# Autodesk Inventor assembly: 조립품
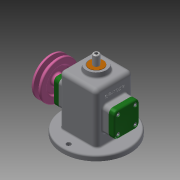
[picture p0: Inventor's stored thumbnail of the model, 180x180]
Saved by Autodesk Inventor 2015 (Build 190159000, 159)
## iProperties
Created: 2021-08
Part Number: 조립품
Document SubType Name: Assembly
Designer: 104-00
Author: 104-00
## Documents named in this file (16)
- C:\Users\104-00\Desktop\710806V1026\조립품.iam
- C:\Users\104-00\Desktop\710806V1026\V벨트풀리.ipt
- C:\Users\104-00\Desktop\710806V1026\고정핀 1.2x8.ipt
- C:\Users\104-00\Desktop\710806V1026\뒤커버.ipt
- C:\Users\104-00\Desktop\710806V1026\링크.ipt
- C:\Users\104-00\Desktop\710806V1026\멈춤나사 M3x8.ipt
- C:\Users\104-00\Desktop\710806V1026\베어링 12x32x10.ipt
- C:\Users\104-00\Desktop\710806V1026\본체.ipt
- C:\Users\104-00\Desktop\710806V1026\볼트 M4.ipt
- C:\Users\104-00\Desktop\710806V1026\부시.ipt
- C:\Users\104-00\Desktop\710806V1026\슬라이드.ipt
- C:\Users\104-00\Desktop\710806V1026\앞커버.ipt
- C:\Users\104-00\Desktop\710806V1026\오일 실 12 25 7.ipt
- C:\Users\104-00\Desktop\710806V1026\키 4x4x10.ipt
- C:\Users\104-00\Desktop\710806V1026\편심축.ipt
- C:\Users\104-00\Desktop\710806V1026\핀 5x18.ipt
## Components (3 placed, 3 different names)
1. V벨트풀리:1 — 각도:2
2. 고정핀 1.2x8:1
3. 핀 5x18:1
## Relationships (1: Angle 1)
- 각도:2 [Angle]: V벨트풀리:1
